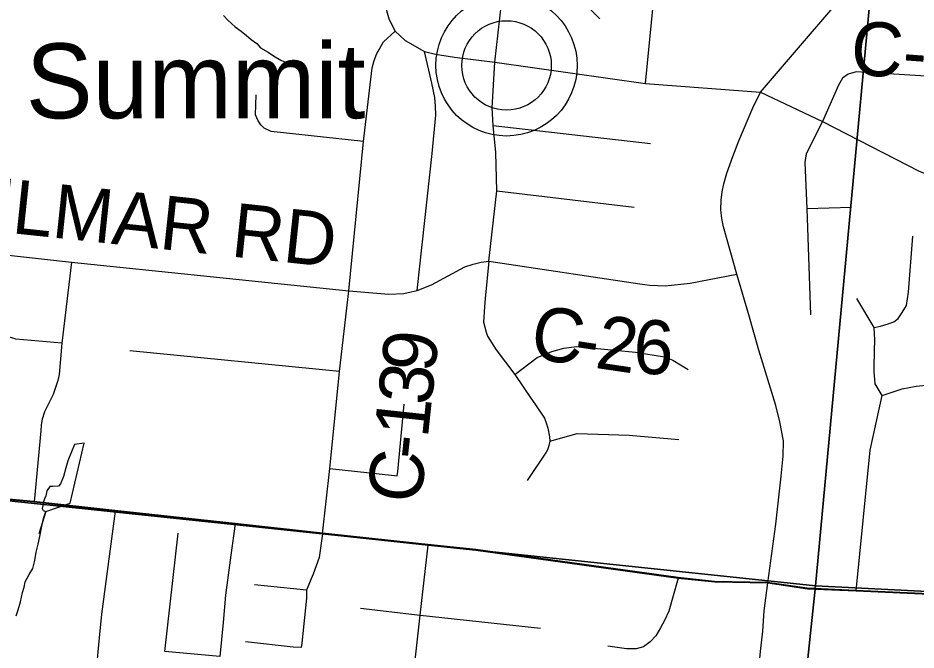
# Model space of a CAD drawing. Extents: x 0 to 43.4, y -8.1 to 22.
# Drawn here: x 6.917 to 7.863, y 17.176 to 17.842 of the extents above; entities that cross this region are included whole.
import ezdxf

# ---------------------------------------------------------------- set-up
doc = ezdxf.new("R2010")
doc.units = 0
for name, color, linetype in [('GM_X_Corporation', 7, 'Continuous'), ('GM_X_County_Road', 7, 'Continuous'), ('GM_X_County_Road_Text', 7, 'Continuous'), ('GM_X_Minor_Lake', 7, 'Continuous'), ('GM_X_Minor_River', 7, 'Continuous'), ('GM_X_Township_Road', 7, 'Continuous'), ('GM_X_Unincorporated', 7, 'Continuous'), ('GM_X_Unincorporated_Location', 7, 'Continuous'), ('GM_X_Unincorporated_Text', 7, 'Continuous')]:
    doc.layers.add(name, color=color, linetype=linetype)

msp = doc.modelspace()

# ---------------------------------------------------------------- linework, layer by layer
at = {"layer": 'GM_X_Corporation'}
for points in [[(6.84307, 18.37989), (7.85258, 18.26744), (7.75749, 17.24308), (6.72714, 17.35166)], [(8.84816, 18.18673), (8.74847, 17.1931), (7.75749, 17.24308), (7.85258, 18.26744)], [(7.75749, 17.24308), (7.65014, 16.22803), (6.62666, 16.41193), (6.72714, 17.35166)], [(7.75749, 17.24308), (8.74847, 17.1931), (8.6363, 16.19901), (7.65014, 16.22803)]]:
    msp.add_lwpolyline(points, close=True, dxfattribs=at)
for points in [[(7.88472, 17.23458), (7.79987, 17.23837), (7.74867, 17.24065), (7.70673, 17.24687), (7.65098, 17.24783), (7.61247, 17.25199), (7.39931, 17.28155), (7.34885, 17.2867), (7.23769, 17.29865), (7.1457, 17.30899), (7.01917, 17.32262), (6.93373, 17.3322), (6.84006, 17.34103)], [(6.84006, 17.34103), (6.93373, 17.3322), (7.01917, 17.32262), (7.1457, 17.30899), (7.23769, 17.29865), (7.34885, 17.2867), (7.39931, 17.28155), (7.61247, 17.25199), (7.65098, 17.24783), (7.70673, 17.24687), (7.74867, 17.24065), (7.79987, 17.23837), (7.88472, 17.23458)]]:
    msp.add_lwpolyline(points, dxfattribs=at)
at = {"layer": 'GM_X_County_Road'}
for points in [[(7.41322, 17.58544), (7.42151, 17.65962), (7.42032, 17.70009), (7.41776, 17.72826), (7.4167, 17.74707), (7.41945, 17.79522), (7.4265, 17.85693), (7.44478, 18.02288), (7.44666, 18.04733), (7.45969, 18.17697), (7.46344, 18.21084), (7.46748, 18.24282), (7.46904, 18.27484), (7.46779, 18.30334)], [(7.296, 17.8829), (7.30756, 17.84072), (7.31436, 17.82773)], [(7.70697, 17.24634), (7.71559, 17.30815), (7.72121, 17.35898), (7.7233, 17.38002), (7.72343, 17.39622), (7.7199, 17.41595), (7.71559, 17.4332), (7.69753, 17.4916), (7.6871, 17.52899), (7.67442, 17.57185), (7.6604, 17.62149), (7.65875, 17.63039), (7.6577, 17.63966), (7.65796, 17.64959), (7.65888, 17.65835), (7.6607, 17.66684), (7.664, 17.67811), (7.67011, 17.69559), (7.67639, 17.71218), (7.69115, 17.7472), (7.69945, 17.7637), (7.74153, 17.81285), (7.79923, 17.88026)], [(7.26544, 17.55408), (7.28098, 17.71151), (7.29013, 17.7893), (7.29211, 17.79687), (7.29522, 17.80444), (7.30212, 17.8167), (7.31436, 17.82773)], [(7.31436, 17.82773), (7.32494, 17.81807), (7.34532, 17.80658), (7.35681, 17.80371), (7.37704, 17.80054), (7.41945, 17.79522), (7.57816, 17.7728), (7.69945, 17.7637)], [(7.69945, 17.7637), (7.76457, 17.73259), (7.8665, 17.68023), (7.9818, 17.63511), (8.11775, 17.58191), (8.1642, 17.56373), (8.17662, 17.55998), (8.19243, 17.55716)], [(6.75503, 17.60849), (6.97346, 17.58455), (7.26544, 17.55408)], [(7.26544, 17.55408), (7.30756, 17.55057), (7.32343, 17.55146), (7.33128, 17.55312), (7.33755, 17.55462), (7.35273, 17.56052), (7.38769, 17.57948), (7.39668, 17.58242), (7.40489, 17.58455), (7.41322, 17.58544), (7.57234, 17.56145), (7.58292, 17.56002), (7.59885, 17.55959), (7.62509, 17.5623), (7.67442, 17.57185)], [(7.23793, 17.29812), (7.24557, 17.36689), (7.25562, 17.46918), (7.26544, 17.55408)], [(6.20646, 17.40487), (6.41909, 17.38519), (6.50244, 17.37748), (6.73053, 17.3523), (6.8403, 17.34051), (6.93397, 17.33168), (7.01941, 17.32209), (7.14594, 17.30847), (7.23793, 17.29812), (7.34909, 17.28618), (7.39955, 17.28102), (7.6127, 17.25147), (7.65122, 17.24731), (7.70697, 17.24634), (7.7489, 17.24012), (7.80011, 17.23784), (7.88496, 17.23405), (7.94383, 17.23145), (8.00436, 17.22962), (8.05662, 17.22804), (8.13919, 17.22316), (8.19428, 17.22139)], [(7.69325, 16.66276), (7.69899, 16.72496), (7.70539, 16.79174), (7.70605, 16.80885), (7.70507, 16.89638), (7.70788, 16.93665), (7.71154, 16.97964), (7.71187, 17.00934), (7.71193, 17.0212), (7.71128, 17.02799), (7.69808, 17.08718), (7.69612, 17.10717), (7.69454, 17.12252), (7.69459, 17.13174), (7.69716, 17.15265), (7.69923, 17.17421), (7.702, 17.19538), (7.70331, 17.21681), (7.70697, 17.24634)]]:
    msp.add_lwpolyline(points, dxfattribs=at)
at = {"layer": 'GM_X_Minor_Lake'}
for points in [[(6.9462, 17.32167), (6.97179, 17.33028), (6.98676, 17.39368), (6.97647, 17.39205), (6.97324, 17.38455), (6.96957, 17.37515), (6.96747, 17.36761), (6.96495, 17.35857), (6.96171, 17.35068), (6.95975, 17.34845), (6.95366, 17.34786), (6.95062, 17.34793), (6.94747, 17.34346), (6.94619, 17.33818), (6.94496, 17.33479)], [(6.94496, 17.33479), (6.94362, 17.33064), (6.94312, 17.328), (6.94249, 17.32462), (6.94362, 17.32274), (6.9462, 17.32167)]]:
    msp.add_lwpolyline(points, dxfattribs=at)
at = {"layer": 'GM_X_Minor_River'}
for points in [[(7.13354, 17.84432), (7.13793, 17.83961), (7.14566, 17.8325), (7.15195, 17.82772), (7.15787, 17.82333), (7.16266, 17.81899), (7.16859, 17.81498), (7.17261, 17.81028), (7.18043, 17.80583), (7.18636, 17.80182), (7.1938, 17.79738), (7.20016, 17.7945)], [(6.91517, 17.21161), (6.9172, 17.21803), (6.91964, 17.22636), (6.92173, 17.2362), (6.92336, 17.24187), (6.92461, 17.24755), (6.92857, 17.25508), (6.9325, 17.26148), (6.93456, 17.2698), (6.93626, 17.2789), (6.93832, 17.28722), (6.93999, 17.29518), (6.9421, 17.30616), (6.94377, 17.31411), (6.9462, 17.32167), (6.9389, 17.29823)]]:
    msp.add_lwpolyline(points, dxfattribs=at)
at = {"layer": 'GM_X_Township_Road'}
for p, q in [((7.50463, 17.86611), (7.53001, 17.84078)), ((7.41776, 17.72826), (7.58338, 17.70931)), ((7.42151, 17.65962), (7.56639, 17.64224)), ((7.74816, 17.64091), (7.79541, 17.64226)), ((7.41322, 17.58544), (7.4094, 17.54611)), ((7.25562, 17.46918), (7.03492, 17.49088)), ((7.22112, 17.23859), (7.16626, 17.2443))]:
    msp.add_line(p, q, dxfattribs=at)
for points in [[(7.57816, 17.7728), (7.59263, 17.91969), (7.59462, 17.93759), (7.60527, 18.03347), (7.60738, 18.05693), (7.61338, 18.12015)], [(7.33755, 17.55462), (7.35329, 17.69884), (7.35725, 17.73919), (7.35694, 17.74897), (7.35605, 17.7581), (7.35303, 17.77305), (7.34532, 17.80658)], [(8.14057, 17.64294), (8.08032, 17.66551), (8.03464, 17.68166), (8.02698, 17.6862), (8.0213, 17.69107), (8.01796, 17.6987), (8.0173, 17.70859), (8.01819, 17.72035), (8.02148, 17.751), (8.0197, 17.75877), (8.01636, 17.76368), (8.01152, 17.76833), (8.00427, 17.77156), (7.99805, 17.77275), (7.80019, 17.78507), (7.79183, 17.78268), (7.78561, 17.77838), (7.78142, 17.77085), (7.76457, 17.73259), (7.74735, 17.69863), (7.74591, 17.68931), (7.74816, 17.64091), (7.75208, 17.52884)], [(7.28098, 17.71151), (7.18385, 17.72214), (7.17645, 17.72577), (7.17267, 17.72909), (7.1701, 17.73347), (7.16739, 17.73952), (7.16754, 17.75009), (7.16799, 17.76081)], [(7.81924, 17.5156), (7.8259, 17.51686), (7.834, 17.51938), (7.83995, 17.52154), (7.84427, 17.52496), (7.84859, 17.53127), (7.85327, 17.53865), (7.85543, 17.55287), (7.86003, 17.61174)], [(6.97346, 17.58455), (6.96314, 17.4989), (6.9602, 17.46593), (6.95909, 17.45968), (6.95725, 17.45433), (6.95393, 17.44476), (6.94491, 17.42652), (6.94233, 17.41879), (6.94123, 17.41289), (6.94086, 17.40645), (6.93397, 17.33168)], [(7.4094, 17.54611), (7.40854, 17.53726), (7.40763, 17.52125), (7.41022, 17.51046), (7.41161, 17.50639), (7.42069, 17.49211), (7.44056, 17.46596), (7.45746, 17.44098)], [(7.81969, 17.49876), (7.81978, 17.50263), (7.81942, 17.50876), (7.81924, 17.5156), (7.80105, 17.54603)], [(6.96314, 17.4989), (6.91452, 17.50332), (6.90384, 17.50664), (6.88966, 17.51106), (6.8484, 17.52451), (6.82004, 17.53371), (6.79278, 17.5374), (6.74809, 17.54156)], [(7.80011, 17.23784), (7.81506, 17.38611), (7.82752, 17.44393), (7.82014, 17.456), (7.81902, 17.46918), (7.8196, 17.49489), (7.81969, 17.49876)], [(7.44056, 17.46596), (7.46413, 17.48379), (7.47948, 17.49007), (7.49207, 17.49391), (7.50575, 17.49544), (7.56769, 17.48963), (7.59822, 17.48465), (7.60683, 17.48101), (7.62323, 17.4711)], [(7.82752, 17.44393), (7.84877, 17.45078), (7.86353, 17.45366), (7.87398, 17.45474), (7.89018, 17.45185), (7.91143, 17.45006), (7.96113, 17.44573), (7.98165, 17.43565), (8.02415, 17.409), (8.09798, 17.37947), (8.16856, 17.35354), (8.1979, 17.34488)], [(7.24557, 17.36689), (7.31353, 17.35939), (7.31651, 17.35933), (7.31719, 17.36386), (7.3239, 17.43467)], [(7.45746, 17.44098), (7.46141, 17.43515), (7.47168, 17.42004), (7.47349, 17.41506), (7.47531, 17.40947), (7.47711, 17.40041), (7.47727, 17.39556), (7.4758, 17.3898), (7.47505, 17.38675), (7.47365, 17.3843), (7.45336, 17.35433)], [(7.47727, 17.39556), (7.50627, 17.40373), (7.56103, 17.40193), (7.61316, 17.39752)], [(7.01941, 17.32209), (7.00508, 17.21329), (7.00263, 17.18831), (6.99624, 17.1217), (6.98211, 16.97805), (6.97254, 16.87602)], [(7.14594, 17.30847), (7.14115, 17.2755), (7.13544, 17.23351), (7.13305, 17.20459), (7.12968, 17.16861), (7.0718, 17.17415), (7.08572, 17.29872)], [(7.23793, 17.29812), (7.23433, 17.27305), (7.22788, 17.25546), (7.22484, 17.24813), (7.22112, 17.23859), (7.22088, 17.23017), (7.21593, 17.18286), (7.21547, 17.17816), (7.20699, 17.17844), (7.15653, 17.18424)], [(7.32745, 17.0905), (7.33417, 17.15229), (7.3408, 17.21251), (7.34909, 17.28618)], [(7.6127, 17.25147), (7.60266, 17.21642), (7.59826, 17.20656), (7.59385, 17.19898), (7.58892, 17.1907), (7.58328, 17.18418), (7.57606, 17.17889), (7.5683, 17.17695), (7.55808, 17.17695), (7.53864, 17.17974)], [(7.27799, 17.21988), (7.3408, 17.21251), (7.46751, 17.1987)]]:
    msp.add_lwpolyline(points, dxfattribs=at)
at = {"layer": 'GM_X_Unincorporated'}
for radius in [0.0744, 0.04716]:
    msp.add_circle((7.43177, 17.79174), radius, dxfattribs=at)
at = {"layer": 'GM_X_Unincorporated_Location'}
msp.add_line((7.43177, 17.79174), (7.43177, 17.79174), dxfattribs=at)

# ---------------------------------------------------------------- texts
at = {"layer": 'GM_X_County_Road_Text'}
for s, height, rotation, p in [('C-126', 0.056818, 355.87541, (7.79307, 17.78253)), ('JULMAR RD', 0.056818, 353.92776, (6.81703, 17.62488)), ('C', 0.05682, 351.42744, (7.45504, 17.48353)), ('2', 0.05682, 351.55156, (7.52384, 17.47317)), ('6', 0.05682, 357.28433, (7.56436, 17.46746)), ('9', 0.05682, 83.91941, (7.35613, 17.46704)), ('-', 0.05682, 351.44313, (7.50086, 17.47663)), ('3', 0.05682, 83.88705, (7.35243, 17.43248)), ('1', 0.05682, 83.86916, (7.34872, 17.39794)), ('-', 0.05682, 83.86615, (7.34624, 17.37494)), ('C', 0.05682, 83.86597, (7.3413, 17.32889))]:
    msp.add_text(s, height=height, rotation=rotation, dxfattribs=at).set_placement(p)
at = {"layer": 'GM_X_Unincorporated_Text'}
msp.add_text('Summit', height=0.078977, rotation=0.00001, dxfattribs=at).set_placement((6.92517, 17.73596))

doc.saveas('drawing.dxf')
